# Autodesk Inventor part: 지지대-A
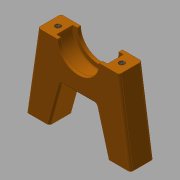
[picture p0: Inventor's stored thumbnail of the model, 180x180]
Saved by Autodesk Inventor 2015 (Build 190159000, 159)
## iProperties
Created: 2018-01
Part Number: 지지대-A
Material: 일반
Document SubType Name: Modeling
Designer: mduedu
Density: 1 g/cm^3
Appearance: 주황색
Mass: 8.09801 g
Surface Area: 38.5771 cm^2
Volume: 8.09801 cm^3
Author: mduedu
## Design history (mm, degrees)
sketch "스케치1"
  geometry: L1 (-22.5, 0)-(22.5, 0); L2 (22.5, 0)-(17.5, 34); L3 (17.5, 34)-(-17.5, 34); L4 (-17.5, 34)-(-22.5, 0); 3 further points
  constraints: 8 end point, 2 midpoint, 1 coincident, 1 horizontal, 1 parallel, 1 vertical alignment
  dimensions: "d0" = 45 distance of L1.start L1.end; "d3" = 35 distance of L2.end L3.end; "d4" = 34 vertical distance of L1.end L2.end
extrude "돌출1" new body sketch "스케치1" stored distance "d5" = 10; taper "d6" = 0 deg
sketch "스케치2"
  geometry: L1 (-12.5, 0)-(12.5, 0); L2 (12.5, 0)-(7.5, 18); L3 (7.5, 18)-(-7.5, 18); L4 (-7.5, 18)-(-12.5, 0); L5 (-22.5, 0)-(22.5, 0) reference; 4 further points
  constraints: 8 end point, 4 midpoint, 1 horizontal, 1 parallel, 1 vertical alignment
  dimensions: "d7" = 10 distance of L1.start L5.start; "d8" = 10 distance of L1.end L5.end (derived); "d9" = 15 distance of L2.end L3.end; "d10" = 18 distance between parallel lines of L1 L3
extrude "돌출2" cut sketch "스케치2" stored distance "d11" = 10; taper "d12" = 0 deg
sketch "스케치3"
  geometry: L1 (-17.5, 34)-(17.5, 34) reference; C1 r 11 at (0, 34); C2 r 9 at (0, 34); 1 further point
  constraints: 2 centre point, 1 coincident, 1 midpoint
  dimensions: "d13" = 22 diameter of C1; "d16" = 18 diameter of C2
extrude "돌출3" cut sketch "스케치3" stored distance "d14" = 7; taper "d15" = 0 deg
extrude "돌출4" cut sketch "스케치3" stored distance "d17" = 7; taper "d18" = 0 deg
fillet "모깎기1" dims "d19" = 0.3
fillet "모깎기2" dims "d20" = 1
fillet "모깎기3" dims "d21" = 1
fillet "모깎기4" dims "d22" = 1
sketch "스케치4"
  geometry: 2 further points
  constraints: 2 other
hole "구멍1" sketch "스케치4" at (-22.771, -3.5), (4.771, -3.5) diameter "d23" = 2.459; stored, may be unused: countersink angle "d27" = 90 deg, drill point angle "d29" = 120 deg; dims "d24" = 4.5, "d25" = 4, "d26" = 2, "d28" = 6
sketch "스케치5"
  geometry: 4 further points
  constraints: 4 other
hole "구멍2" sketch "스케치5" at (40, 4), (5, -27), (40, -27), (5, 4) diameter "d30" = 2.459; stored, may be unused: countersink angle "d34" = 90 deg, drill point angle "d36" = 120 deg; dims "d31" = 6.9, "d32" = 4, "d33" = 2, "d35" = 8.4
node "솔리드1"
